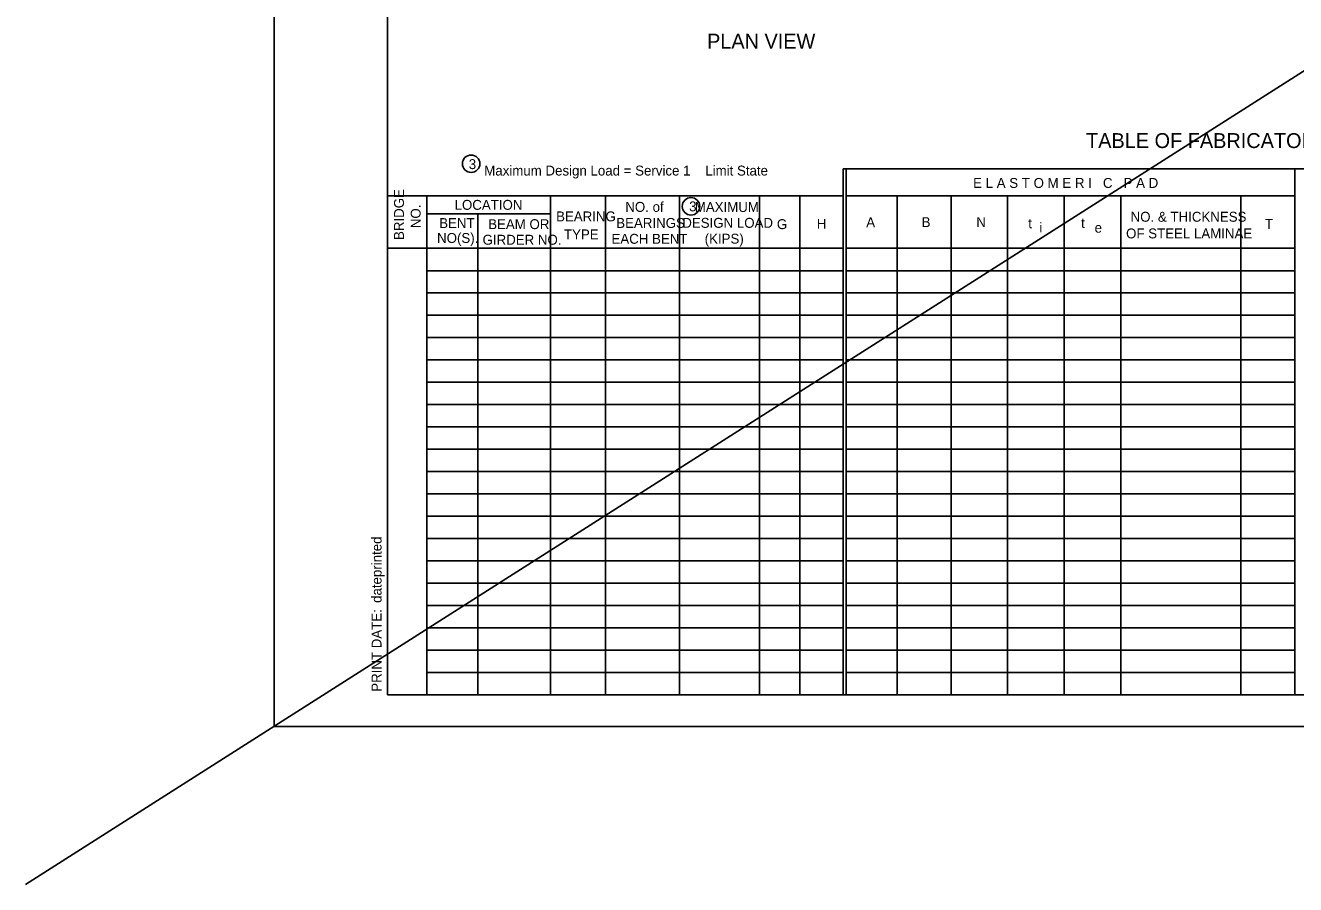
# Model space of a CAD drawing. Extents: x 113 to 232, y -103 to -27.
# Drawn here: x 174.6 to 185.26, y -61.87 to -54.65 of the extents above; entities that cross this region are included whole.
import ezdxf

# ---------------------------------------------------------------- set-up
doc = ezdxf.new("R2010")
doc.units = 0
for name, color, linetype in [('1', 7, 'Continuous'), ('B_Border', 7, 'Continuous'), ('B_No_Plot', 7, 'Continuous')]:
    doc.layers.add(name, color=color, linetype=linetype)

msp = doc.modelspace()

# ---------------------------------------------------------------- linework, layer by layer
at = {"layer": '1'}
for p, q in [((174.602, -61.87), (200.873, -45.138)), ((181.465, -55.859), (181.465, -56.086)), ((185.762, -55.859), (181.465, -55.859)), ((181.49, -55.859), (181.49, -56.086)), ((185.255, -55.859), (185.255, -56.086)), ((179.008, -56.086), (177.641, -56.086)), ((177.97, -56.086), (177.97, -60.276)), ((179.008, -56.086), (179.008, -60.276)), ((179.008, -56.086), (179.008, -60.276)), ((181.465, -56.086), (179.008, -56.086)), ((179.47, -56.086), (179.47, -60.276)), ((180.091, -56.086), (180.091, -60.276)), ((180.763, -56.086), (180.763, -60.276)), ((181.102, -56.086), (181.102, -60.276)), ((181.465, -56.086), (181.465, -60.276)), ((183.821, -56.086), (181.49, -56.086)), ((181.49, -56.086), (181.49, -60.276)), ((181.92, -56.086), (181.92, -60.276)), ((182.371, -56.086), (182.371, -60.276)), ((182.371, -56.086), (182.371, -60.276)), ((182.846, -56.086), (182.846, -60.276)), ((183.321, -56.086), (183.321, -60.276)), ((183.797, -56.086), (183.797, -60.276)), ((185.255, -56.086), (183.814, -56.086)), ((184.804, -56.086), (184.804, -60.276)), ((185.255, -56.086), (185.255, -60.276)), ((179.008, -56.237), (177.97, -56.237)), ((178.4, -56.237), (178.4, -60.281)), ((177.951, -56.526), (177.641, -56.526)), ((179.008, -56.526), (177.951, -56.526)), ((181.465, -56.526), (179.008, -56.526)), ((184.796, -56.526), (181.49, -56.526)), ((185.255, -56.526), (184.796, -56.526)), ((179.008, -56.714), (177.97, -56.714)), ((181.465, -56.714), (179.008, -56.714)), ((184.796, -56.714), (181.49, -56.714)), ((185.255, -56.714), (184.796, -56.714)), ((179.008, -56.901), (177.97, -56.901)), ((181.465, -56.901), (179.008, -56.901)), ((184.796, -56.901), (181.49, -56.901)), ((185.255, -56.901), (184.796, -56.901)), ((179.008, -57.089), (177.97, -57.089)), ((181.465, -57.089), (179.008, -57.089)), ((184.796, -57.089), (181.49, -57.089)), ((185.255, -57.089), (184.796, -57.089)), ((179.008, -57.276), (177.97, -57.276)), ((181.465, -57.276), (179.008, -57.276)), ((184.796, -57.276), (181.49, -57.276)), ((185.255, -57.276), (184.796, -57.276)), ((179.008, -57.464), (177.97, -57.464)), ((181.465, -57.464), (179.008, -57.464)), ((184.796, -57.464), (181.49, -57.464)), ((185.255, -57.464), (184.796, -57.464)), ((179.008, -57.651), (177.97, -57.651)), ((181.465, -57.651), (179.008, -57.651)), ((184.796, -57.651), (181.49, -57.651)), ((185.255, -57.651), (184.796, -57.651)), ((179.008, -57.839), (177.97, -57.839)), ((181.465, -57.839), (179.008, -57.839)), ((184.796, -57.839), (181.49, -57.839)), ((185.255, -57.839), (184.796, -57.839)), ((179.008, -58.026), (177.97, -58.026)), ((181.465, -58.026), (179.008, -58.026)), ((184.796, -58.026), (181.49, -58.026)), ((185.255, -58.026), (184.796, -58.026)), ((179.008, -58.214), (177.97, -58.214)), ((181.465, -58.214), (179.008, -58.214)), ((184.796, -58.214), (181.49, -58.214)), ((185.255, -58.214), (184.796, -58.214)), ((179.008, -58.401), (177.97, -58.401)), ((181.465, -58.401), (179.008, -58.401)), ((184.796, -58.401), (181.49, -58.401)), ((185.255, -58.401), (184.796, -58.401)), ((179.008, -58.589), (177.97, -58.589)), ((181.465, -58.589), (179.008, -58.589)), ((184.796, -58.589), (181.49, -58.589)), ((185.255, -58.589), (184.796, -58.589)), ((179.008, -58.776), (177.97, -58.776)), ((181.465, -58.776), (179.008, -58.776)), ((184.796, -58.776), (181.49, -58.776)), ((185.255, -58.776), (184.796, -58.776)), ((179.008, -58.964), (177.97, -58.964)), ((181.465, -58.964), (179.008, -58.964)), ((184.796, -58.964), (181.49, -58.964)), ((185.255, -58.964), (184.796, -58.964)), ((179.008, -59.151), (177.97, -59.151)), ((181.465, -59.151), (179.008, -59.151)), ((184.796, -59.151), (181.49, -59.151)), ((185.255, -59.151), (184.796, -59.151)), ((179.008, -59.339), (177.97, -59.339)), ((181.465, -59.339), (179.008, -59.339)), ((184.796, -59.339), (181.49, -59.339)), ((185.255, -59.339), (184.796, -59.339)), ((179.008, -59.526), (177.97, -59.526)), ((181.465, -59.526), (179.008, -59.526)), ((184.796, -59.526), (181.49, -59.526)), ((185.255, -59.526), (184.796, -59.526)), ((179.008, -59.714), (177.97, -59.714)), ((181.465, -59.714), (179.008, -59.714)), ((184.796, -59.714), (181.49, -59.714)), ((185.255, -59.714), (184.796, -59.714)), ((179.008, -59.901), (177.97, -59.901)), ((181.465, -59.901), (179.008, -59.901)), ((184.796, -59.901), (181.49, -59.901)), ((185.255, -59.901), (184.796, -59.901)), ((179.008, -60.089), (177.97, -60.089)), ((181.465, -60.089), (179.008, -60.089)), ((184.796, -60.089), (181.49, -60.089)), ((185.255, -60.089), (184.796, -60.089)), ((177.951, -60.276), (177.641, -60.276)), ((181.465, -60.276), (181.4, -60.276))]:
    msp.add_line(p, q, dxfattribs=at)
for centre in [(178.343, -55.816), (180.188, -56.174)]:
    msp.add_circle(centre, 0.0733, dxfattribs=at)
at = {"layer": 'B_Border'}
for p, q in [((177.64, -60.277), (177.64, -46.58)), ((177.641, -60.276), (177.641, -46.58)), ((198.717, -60.277), (177.64, -60.277))]:
    msp.add_line(p, q, dxfattribs=at)
at = {"layer": 'B_No_Plot'}
msp.add_lwpolyline([(176.689, -46.317), (199.022, -46.317), (199.022, -60.541), (176.689, -60.541)], close=True, dxfattribs=at)

# ---------------------------------------------------------------- texts
at = {"layer": '1'}
for s, height, p in [('PLAN VIEW', 0.1248, (180.323, -54.849)), ('TABLE OF FABRICATOR VARIABLES', 0.12483, (183.504, -55.684)), ('3', 0.0833, (178.323, -55.861)), ('Maximum Design Load = Service 1    Limit State', 0.08333, (178.453, -55.915)), ('E L A S T O M E R I   C   P A D', 0.08333, (182.556, -56.019)), ('LOCATION', 0.0833, (178.204, -56.203)), ('NO. of ', 0.0833, (179.637, -56.22)), ('3', 0.0833, (180.173, -56.216)), ('  MAXIMUM', 0.0833, (180.158, -56.221)), ('BENT', 0.0833, (178.075, -56.356)), ('BEAM OR', 0.0833, (178.486, -56.365)), ('BEARING', 0.0833, (179.056, -56.3)), ('BEARINGS', 0.0833, (179.561, -56.355)), ('DESIGN LOAD', 0.08333, (180.115, -56.354)), ('G', 0.0833, (180.909, -56.365)), ('H', 0.0833, (181.244, -56.362)), ('A', 0.0833, (181.659, -56.349)), ('B', 0.0833, (182.124, -56.348)), ('N', 0.0833, (182.583, -56.348)), ('t', 0.0833, (183.019, -56.358)), (' t ', 0.0833, (183.431, -56.356)), ('NO. & THICKNESS', 0.08333, (183.878, -56.303)), ('T', 0.0833, (185.005, -56.363)), ('NO(S).', 0.0833, (178.057, -56.481)), ('TYPE', 0.0833, (179.122, -56.451)), ('i', 0.0833, (183.112, -56.393)), ('e', 0.0833, (183.576, -56.395)), ('OF STEEL LAMINAE', 0.08333, (183.84, -56.443)), ('GIRDER NO.', 0.0833, (178.439, -56.496)), ('EACH BENT', 0.0833, (179.521, -56.488)), ('(KIPS)', 0.0833, (180.303, -56.487))]:
    msp.add_text(s, height=height, dxfattribs=at).set_placement(p)
for s, p in [('BRIDGE', (177.779, -56.456)), ('NO.', (177.919, -56.357))]:
    msp.add_text(s, height=0.0833, rotation=90, dxfattribs=at).set_placement(p)
at = {"layer": 'B_Border'}
for s, p in [('dateprinted', (177.591, -59.504)), ('PRINT DATE:  ', (177.591, -60.25))]:
    msp.add_text(s, height=0.08333, rotation=90, dxfattribs=at).set_placement(p)

doc.saveas('drawing.dxf')
